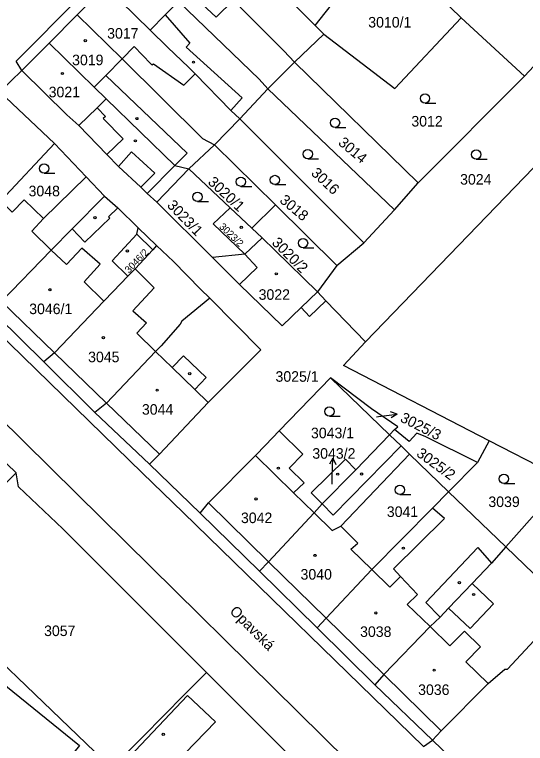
# Model space of a CAD drawing. Extents: x -527335 to -526256, y -1079142 to -1077836.
# Drawn here: x -526659.5 to -526577.1, y -1078831.7 to -1078714.2 of the extents above; entities that cross this region are included whole.
import ezdxf

# ---------------------------------------------------------------- set-up
doc = ezdxf.new("R2010")
doc.units = 0
for name, color, linetype in [('Hranice parcel', 7, 'Continuous'), ('Parcelní čísla', 7, 'Continuous'), ('Pop  PČ popisy', 7, 'Continuous'), ('Vnitřní kresba', 7, 'Continuous'), ('Značky budov', 7, 'Continuous'), ('Značky kultur', 7, 'Continuous')]:
    doc.layers.add(name, color=color, linetype=linetype)

msp = doc.modelspace()

# ---------------------------------------------------------------- linework, layer by layer
at = {"layer": 'Hranice parcel'}
for p, q in [((-526587.53, -1078714.71), (-526598.14, -1078704.26)), ((-526649.43, -1078714.21), (-526644.88, -1078709.64)), ((-526653.96, -1078718.78), (-526649.43, -1078714.21)), ((-526587.53, -1078714.71), (-526577.27, -1078724.14)), ((-526577.27, -1078724.14), (-526569.24, -1078715.32)), ((-526611.06, -1078715.96), (-526609.66, -1078717.36)), ((-526614.38, -1078721.84), (-526609.66, -1078717.36)), ((-526658.35, -1078723.2), (-526653.96, -1078718.78)), ((-526618.7, -1078726.19), (-526614.38, -1078721.84)), ((-526614.38, -1078721.84), (-526594.44, -1078741.33)), ((-526658.35, -1078723.2), (-526661.96, -1078726.67)), ((-526594.44, -1078741.33), (-526577.27, -1078724.14)), ((-526661.96, -1078726.67), (-526653.1, -1078734.98)), ((-526623.18, -1078731.02), (-526618.7, -1078726.19)), ((-526618.7, -1078726.19), (-526598.24, -1078745.67)), ((-526627.28, -1078735.22), (-526623.18, -1078731.02)), ((-526623.18, -1078731.02), (-526603.21, -1078751.02)), ((-526602.93, -1078766.96), (-526568.24, -1078730.99)), ((-526653.1, -1078734.98), (-526661.77, -1078744.22)), ((-526653.1, -1078734.98), (-526647.98, -1078740.34)), ((-526631.45, -1078739.09), (-526627.28, -1078735.22)), ((-526627.28, -1078735.22), (-526617.47, -1078744.89)), ((-526636.59, -1078744.44), (-526631.45, -1078739.09)), ((-526624.76, -1078745.36), (-526631.45, -1078739.09)), ((-526647.98, -1078740.34), (-526645, -1078743.45)), ((-526598.24, -1078745.67), (-526594.44, -1078741.33)), ((-526627.59, -1078753.38), (-526636.59, -1078744.44)), ((-526621.29, -1078748.61), (-526624.76, -1078745.36)), ((-526621.29, -1078748.61), (-526617.47, -1078744.89)), ((-526617.47, -1078744.89), (-526607.57, -1078754.64)), ((-526603.21, -1078751.02), (-526598.24, -1078745.67)), ((-526639.57, -1078748.56), (-526636.62, -1078751.43)), ((-526619.61, -1078750.18), (-526621.29, -1078748.61)), ((-526619.61, -1078750.18), (-526622.42, -1078752.83)), ((-526607.57, -1078754.64), (-526603.21, -1078751.02)), ((-526622.42, -1078752.83), (-526627.59, -1078753.38)), ((-526607.57, -1078754.64), (-526610.69, -1078758.91)), ((-526609.32, -1078760.34), (-526610.69, -1078758.91)), ((-526602.93, -1078766.96), (-526609.32, -1078760.34)), ((-526654.83, -1078770.18), (-526663.23, -1078761.88)), ((-526646.57, -1078778.36), (-526654.83, -1078770.18)), ((-526608.58, -1078772.78), (-526616.85, -1078781.33)), ((-526599.06, -1078781.96), (-526608.58, -1078772.78)), ((-526637.79, -1078786.68), (-526646.57, -1078778.36)), ((-526598.24, -1078781.1), (-526599.06, -1078781.96)), ((-526599.06, -1078781.96), (-526604.48, -1078787.61)), ((-526659.25, -1078788.06), (-526664.27, -1078783.3)), ((-526583, -1078782.94), (-526584.89, -1078786.43)), ((-526606.9, -1078796.68), (-526595.85, -1078785.05)), ((-526589.53, -1078791.15), (-526595.85, -1078785.05)), ((-526637.79, -1078786.68), (-526629.58, -1078794.56)), ((-526584.89, -1078786.43), (-526589.53, -1078791.15)), ((-526674.52, -1078803.28), (-526659.25, -1078788.06)), ((-526580.33, -1078800.02), (-526571, -1078789.45)), ((-526589.53, -1078791.15), (-526592.12, -1078793.79)), ((-526580.33, -1078800.02), (-526589.53, -1078791.15)), ((-526609.94, -1078793.08), (-526611.24, -1078794.52)), ((-526592.12, -1078793.79), (-526601.91, -1078803.67)), ((-526620.01, -1078803.95), (-526629.58, -1078794.56)), ((-526580.33, -1078800.02), (-526582.64, -1078802.63)), ((-526570.48, -1078809.52), (-526580.33, -1078800.02)), ((-526620.01, -1078803.95), (-526610.75, -1078813.07)), ((-526610.75, -1078813.07), (-526601.44, -1078822.23)), ((-526615.23, -1078833.62), (-526628.58, -1078820.26)), ((-526601.44, -1078822.23), (-526592.15, -1078831.2))]:
    msp.add_line(p, q, dxfattribs=at)
for points in [[(-526736.02, -1078622.71), (-526735.76, -1078656.09), (-526735.85, -1078660.53), (-526735.52, -1078663.69), (-526734.95, -1078666.12), (-526732.77, -1078674.37), (-526729.8, -1078686.09), (-526729.09, -1078688.53), (-526728.19, -1078690.47), (-526724.67, -1078698.8), (-526723.91, -1078700.57), (-526723.02, -1078702.2), (-526717.26, -1078711.17), (-526716.15, -1078712.7), (-526714.92, -1078714.22), (-526690.33, -1078738.18), (-526681.83, -1078746.32), (-526638.92, -1078788.12), (-526632.34, -1078794.49), (-526593.57, -1078832.2), (-526592.15, -1078831.2)], [(-526611.06, -1078715.96), (-526605, -1078708.2), (-526623.89, -1078688.51)], [(-526631.31, -1078695.96), (-526624.08, -1078702.91), (-526622.14, -1078704.85), (-526618.3, -1078708.7), (-526611.06, -1078715.96)], [(-526635.79, -1078700.47), (-526628.55, -1078707.46), (-526625.07, -1078711.01), (-526624.47, -1078711.62), (-526624.22, -1078711.87), (-526622.06, -1078714.05), (-526616.13, -1078720.06), (-526614.38, -1078721.84)], [(-526640.35, -1078705.07), (-526633.11, -1078712.1), (-526620.07, -1078724.6), (-526618.7, -1078726.19)], [(-526644.88, -1078709.64), (-526637.64, -1078716.69), (-526634.89, -1078719.43), (-526631.42, -1078722.73), (-526630.43, -1078723.74), (-526624.67, -1078729.64), (-526623.18, -1078731.02)], [(-526649.43, -1078714.21), (-526642.17, -1078721.31), (-526629.23, -1078734.17), (-526627.28, -1078735.22)], [(-526609.66, -1078717.36), (-526598.23, -1078726.12), (-526587.53, -1078714.71)], [(-526653.96, -1078718.78), (-526646.7, -1078725.9), (-526644.75, -1078727.79), (-526633.7, -1078738.55), (-526631.45, -1078739.09)], [(-526636.59, -1078744.44), (-526638.15, -1078743.02), (-526639.19, -1078742.04), (-526642.78, -1078738.7), (-526644.65, -1078736.76), (-526649.18, -1078732.07), (-526651.08, -1078730.36), (-526658.35, -1078723.2)], [(-526647.98, -1078740.34), (-526654.86, -1078747.07), (-526657.96, -1078744.05), (-526659.89, -1078746.05), (-526661.77, -1078744.22)], [(-526645, -1078743.45), (-526650.23, -1078748.74), (-526653.6, -1078752.16), (-526661.65, -1078760.47), (-526663.23, -1078761.88)], [(-526645, -1078743.45), (-526642.89, -1078745.33), (-526639.57, -1078748.56)], [(-526622.42, -1078752.83), (-526627.5, -1078747.94), (-526624.76, -1078745.36)], [(-526641.26, -1078756.38), (-526643.79, -1078753.91), (-526639.82, -1078749.58), (-526639.57, -1078748.56)], [(-526610.69, -1078758.91), (-526617.5, -1078752.24), (-526619.61, -1078750.18)], [(-526636.62, -1078751.43), (-526637.23, -1078752.14), (-526640.1, -1078755.16), (-526641.26, -1078756.38)], [(-526636.62, -1078751.43), (-526633.89, -1078754), (-526629.56, -1078758.49), (-526628.06, -1078759.94)], [(-526609.32, -1078760.34), (-526611.96, -1078762.87), (-526613.33, -1078761.44), (-526616.39, -1078764.37), (-526623.24, -1078757.7), (-526627.59, -1078753.38)], [(-526641.26, -1078756.38), (-526643.65, -1078758.85), (-526645.13, -1078760.38), (-526653.11, -1078768.71), (-526654.83, -1078770.18)], [(-526628.06, -1078759.94), (-526632.57, -1078763.6), (-526632.8, -1078764.12), (-526635.9, -1078767.6), (-526636.79, -1078768.49), (-526644.7, -1078776.83), (-526646.57, -1078778.36)], [(-526628.06, -1078759.94), (-526619.84, -1078768.26), (-526628.33, -1078776.71), (-526636.17, -1078785.07), (-526637.79, -1078786.68)], [(-526583, -1078782.94), (-526606.49, -1078770.77), (-526602.93, -1078766.96)], [(-526598.24, -1078781.1), (-526597.7, -1078780.64), (-526601.99, -1078777.75), (-526608.58, -1078772.78)], [(-526584.89, -1078786.43), (-526593.2, -1078782.26), (-526594.65, -1078781.7), (-526595.87, -1078783.03), (-526598.24, -1078781.1)], [(-526629.58, -1078794.56), (-526628.25, -1078792.92), (-526620.7, -1078785.28), (-526619.04, -1078783.6), (-526616.85, -1078781.33)], [(-526616.85, -1078781.33), (-526613.02, -1078785.09), (-526615.22, -1078787.34), (-526612.82, -1078789.68), (-526614.53, -1078791.3), (-526611.24, -1078794.52)], [(-526595.85, -1078785.05), (-526597.21, -1078783.74), (-526599.06, -1078781.96)], [(-526568.95, -1078787.13), (-526573.17, -1078787.97), (-526583, -1078782.94)], [(-526609.94, -1078793.08), (-526611.7, -1078791.28), (-526606.18, -1078785.87), (-526604.48, -1078787.61)], [(-526628.58, -1078820.26), (-526651.76, -1078797.09), (-526658.89, -1078790.32), (-526659.25, -1078788.06)], [(-526604.48, -1078787.61), (-526604.69, -1078787.82), (-526609.94, -1078793.08)], [(-526659.11, -1078844.46), (-526705.02, -1078807.32), (-526694.99, -1078794.92), (-526649.08, -1078832.06), (-526659.11, -1078844.46)], [(-526611.24, -1078794.52), (-526618.56, -1078802.42), (-526620.01, -1078803.95)], [(-526601.91, -1078803.67), (-526605.28, -1078800.36), (-526604.15, -1078799.44), (-526606.9, -1078796.68)], [(-526674.52, -1078803.28), (-526675.67, -1078805.16), (-526643.83, -1078835.71)], [(-526582.64, -1078802.63), (-526585.74, -1078805.91), (-526589.53, -1078809.92), (-526590.9, -1078811.36), (-526592.53, -1078812.87), (-526600, -1078820.6), (-526601.44, -1078822.23)], [(-526601.91, -1078803.67), (-526609.3, -1078811.48), (-526610.75, -1078813.07)], [(-526592.15, -1078831.2), (-526590.73, -1078829.68), (-526583.18, -1078822.03), (-526580.48, -1078819.73), (-526580.05, -1078819.71), (-526573.56, -1078812.8)], [(-526643.83, -1078835.71), (-526634.9, -1078826.67), (-526632.69, -1078824.43), (-526628.58, -1078820.26)], [(-526631.64, -1078823.97), (-526642.87, -1078835.86), (-526638.55, -1078840.04), (-526627.14, -1078828.22), (-526631.64, -1078823.97)], [(-526592.15, -1078831.2), (-526581.94, -1078841.02), (-526570.51, -1078852.02), (-526552.02, -1078869.8)]]:
    msp.add_lwpolyline(points, dxfattribs=at)
at = {"layer": 'Pop  PČ popisy'}
for p, q in [((-526600.83, -1078778.98), (-526597.85, -1078778.61)), ((-526597.85, -1078778.61), (-526598.91, -1078778.24)), ((-526597.85, -1078778.61), (-526598.78, -1078779.23)), ((-526601.17, -1078779.02), (-526600.83, -1078778.98)), ((-526608.2, -1078785.7), (-526608.73, -1078786.68)), ((-526608.3, -1078788.7), (-526608.2, -1078785.7)), ((-526608.2, -1078785.7), (-526607.73, -1078786.72)), ((-526608.33, -1078789.89), (-526608.3, -1078788.7))]:
    msp.add_line(p, q, dxfattribs=at)
at = {"layer": 'Vnitřní kresba'}
for p, q in [((-526659.29, -1078721.72), (-526631.42, -1078693.62)), ((-526635.23, -1078714.25), (-526633.11, -1078712.1)), ((-526637.64, -1078716.69), (-526635.23, -1078714.25)), ((-526635.23, -1078714.25), (-526631.26, -1078718.78)), ((-526631.26, -1078718.78), (-526631.87, -1078719.46)), ((-526642.17, -1078721.31), (-526640.24, -1078719.35)), ((-526640.24, -1078719.35), (-526637.56, -1078722.13)), ((-526631.87, -1078719.46), (-526622.85, -1078727.63)), ((-526658.35, -1078723.2), (-526659.29, -1078721.72)), ((-526644.82, -1078723.99), (-526642.17, -1078721.31)), ((-526637.56, -1078722.13), (-526637.37, -1078722.32)), ((-526637.37, -1078722.32), (-526637.13, -1078722.15)), ((-526637.13, -1078722.15), (-526632.25, -1078725.57)), ((-526644.82, -1078723.99), (-526646.7, -1078725.9)), ((-526631.7, -1078736.54), (-526644.82, -1078723.99)), ((-526632.25, -1078725.57), (-526630.43, -1078723.74)), ((-526646.23, -1078729.22), (-526644.75, -1078727.79)), ((-526622.85, -1078727.63), (-526624.67, -1078729.64)), ((-526649.18, -1078732.07), (-526646.23, -1078729.22)), ((-526646.23, -1078729.22), (-526644.87, -1078730.62)), ((-526644.87, -1078730.62), (-526645.23, -1078730.97)), ((-526645.23, -1078730.97), (-526642, -1078734.21)), ((-526642, -1078734.21), (-526644.65, -1078736.76)), ((-526642.78, -1078738.7), (-526640.69, -1078736.32)), ((-526640.69, -1078736.32), (-526636.89, -1078739.74)), ((-526631.7, -1078736.54), (-526633.7, -1078738.55)), ((-526633.7, -1078738.55), (-526638.15, -1078743.02)), ((-526636.89, -1078739.74), (-526639.19, -1078742.04)), ((-526644.39, -1078746.78), (-526642.89, -1078745.33)), ((-526654.86, -1078747.07), (-526656.74, -1078749.11)), ((-526648.19, -1078750.86), (-526644.19, -1078747)), ((-526644.19, -1078747), (-526644.39, -1078746.78)), ((-526649.54, -1078791.39), (-526693.26, -1078748.65)), ((-526656.74, -1078749.11), (-526653.6, -1078752.16)), ((-526650.23, -1078748.74), (-526648.19, -1078750.86)), ((-526637.23, -1078752.14), (-526639.82, -1078749.58)), ((-526651.18, -1078754.51), (-526653.6, -1078752.16)), ((-526648.69, -1078751.88), (-526651.18, -1078754.51)), ((-526645.72, -1078754.44), (-526648.69, -1078751.88)), ((-526622.42, -1078752.83), (-526620.38, -1078754.98)), ((-526648.33, -1078757.27), (-526645.72, -1078754.44)), ((-526640.1, -1078755.16), (-526637.03, -1078758.23)), ((-526620.38, -1078754.98), (-526623.24, -1078757.7)), ((-526645.13, -1078760.38), (-526648.33, -1078757.27)), ((-526637.03, -1078758.23), (-526640.44, -1078761.95)), ((-526613.33, -1078761.44), (-526610.69, -1078758.91)), ((-526661.65, -1078760.47), (-526653.11, -1078768.71)), ((-526640.44, -1078761.95), (-526638.27, -1078763.9)), ((-526639.8, -1078765.56), (-526638.27, -1078763.9)), ((-526636.79, -1078768.49), (-526639.8, -1078765.56)), ((-526644.7, -1078776.83), (-526653.11, -1078768.71)), ((-526634.12, -1078771.08), (-526636.79, -1078768.49)), ((-526632.31, -1078769.22), (-526634.12, -1078771.08)), ((-526628.61, -1078772.7), (-526632.31, -1078769.22)), ((-526630.48, -1078774.62), (-526634.12, -1078771.08)), ((-526630.48, -1078774.62), (-526628.61, -1078772.7)), ((-526628.33, -1078776.71), (-526630.48, -1078774.62)), ((-526636.17, -1078785.07), (-526644.7, -1078776.83)), ((-526608.16, -1078794.9), (-526597.21, -1078783.74)), ((-526614.53, -1078791.3), (-526620.7, -1078785.28)), ((-526598.1, -1078842.1), (-526649.54, -1078791.39)), ((-526618.56, -1078802.42), (-526628.25, -1078792.92)), ((-526609.94, -1078793.08), (-526608.16, -1078794.9)), ((-526590.17, -1078795.43), (-526592.12, -1078793.79)), ((-526608.31, -1078797.39), (-526611.24, -1078794.52)), ((-526598.44, -1078803.57), (-526590.17, -1078795.43)), ((-526608.31, -1078797.39), (-526606.9, -1078796.68)), ((-526584.83, -1078800.13), (-526593.19, -1078808.99)), ((-526584.83, -1078800.13), (-526582.64, -1078802.63)), ((-526609.3, -1078811.48), (-526618.56, -1078802.42)), ((-526599.02, -1078806.5), (-526601.91, -1078803.67)), ((-526597.31, -1078804.77), (-526598.44, -1078803.57)), ((-526597.31, -1078804.77), (-526599.02, -1078806.5)), ((-526594.57, -1078807.69), (-526597.31, -1078804.77)), ((-526596.19, -1078809.28), (-526594.57, -1078807.69)), ((-526592.53, -1078812.87), (-526596.19, -1078809.28)), ((-526593.19, -1078808.99), (-526590.9, -1078811.36)), ((-526609.3, -1078811.48), (-526600, -1078820.6)), ((-526589.35, -1078815.98), (-526592.53, -1078812.87)), ((-526586.99, -1078813.58), (-526589.35, -1078815.98)), ((-526584.39, -1078816.14), (-526586.99, -1078813.58)), ((-526586.74, -1078818.54), (-526584.39, -1078816.14)), ((-526583.18, -1078822.03), (-526586.74, -1078818.54)), ((-526600, -1078820.6), (-526590.73, -1078829.68))]:
    msp.add_line(p, q, dxfattribs=at)
for points in [[(-526624.22, -1078711.87), (-526627.03, -1078714.61), (-526631.46, -1078710.42)], [(-526585.74, -1078805.91), (-526582.32, -1078809.2), (-526586.08, -1078813.19), (-526589.53, -1078809.92)]]:
    msp.add_lwpolyline(points, dxfattribs=at)
at = {"layer": 'Značky budov'}
for centre in [(-526648.12, -1078718.41), (-526630.67, -1078721.86), (-526651.81, -1078723.7), (-526639.8, -1078730.96), (-526640.05, -1078734.55), (-526646.56, -1078746.95), (-526622.97, -1078748.5), (-526641.34, -1078752.31), (-526617.32, -1078756), (-526653.83, -1078758.56), (-526645.21, -1078766.29), (-526631.29, -1078772.1), (-526636.53, -1078774.74), (-526616.98, -1078787.32), (-526607.42, -1078788.29), (-526603.57, -1078788.27), (-526620.59, -1078792.28), (-526596.83, -1078800.23), (-526611.08, -1078801.39), (-526587.8, -1078805.79), (-526585.5, -1078807.7), (-526601.27, -1078810.66), (-526591.87, -1078819.88), (-526635.54, -1078830.23)]:
    msp.add_circle(centre, 0.175, dxfattribs=at)
at = {"layer": 'Značky kultur'}
for p, q in [((-526593.34, -1078728.46), (-526591.59, -1078728.46)), ((-526607.85, -1078732.39), (-526606.1, -1078732.39)), ((-526612.25, -1078737.44), (-526610.5, -1078737.44)), ((-526585.07, -1078737.5), (-526583.32, -1078737.5)), ((-526654.76, -1078739.76), (-526653.01, -1078739.76)), ((-526623.04, -1078741.89), (-526621.29, -1078741.89)), ((-526617.54, -1078741.61), (-526615.79, -1078741.61)), ((-526630.03, -1078744.34), (-526628.28, -1078744.34)), ((-526613.01, -1078751.78), (-526611.26, -1078751.78)), ((-526608.76, -1078778.94), (-526607.01, -1078778.94)), ((-526580.62, -1078789.79), (-526578.87, -1078789.79)), ((-526597.38, -1078791.57), (-526595.63, -1078791.57))]:
    msp.add_line(p, q, dxfattribs=at)
for centre in [(-526593.34, -1078727.71), (-526607.85, -1078731.64), (-526612.25, -1078736.69), (-526585.07, -1078736.75), (-526654.76, -1078739.01), (-526623.04, -1078741.14), (-526617.54, -1078740.86), (-526630.03, -1078743.59), (-526613.01, -1078751.03), (-526608.76, -1078778.19), (-526580.62, -1078789.04), (-526597.38, -1078790.82)]:
    msp.add_circle(centre, 0.75, dxfattribs=at)

# ---------------------------------------------------------------- texts
at = {"layer": 'Parcelní čísla'}
for s, p in [('3010/1', (-526602.49, -1078716.28)), ('3017', (-526644.6, -1078718.07)), ('3019', (-526650.25, -1078722.36)), ('3021', (-526654.03, -1078727.53)), ('3012', (-526595.54, -1078732.24)), ('3024', (-526587.68, -1078741.61)), ('3048', (-526657.27, -1078743.49)), ('3022', (-526620.17, -1078760.18)), ('3046/1', (-526657.17, -1078762.49)), ('3045', (-526647.67, -1078770.24)), ('3025/1', (-526617.45, -1078773.39)), ('3044', (-526638.99, -1078778.7)), ('3043/1', (-526611.73, -1078782.5)), ('3043/2', (-526611.51, -1078785.8)), ('3039', (-526583.12, -1078793.59)), ('3041', (-526599.5, -1078795.19)), ('3042', (-526623.02, -1078796.18)), ('3040', (-526613.41, -1078805.29)), ('3057', (-526654.77, -1078814.39)), ('3038', (-526603.81, -1078814.53)), ('3036', (-526594.45, -1078823.89))]:
    msp.add_text(s, height=1.7, dxfattribs=at).set_placement(p)
for s, height, rotation, p in [('3014', 1.7, 320, (-526607.46, -1078735.06)), ('3016', 1.7, 317, (-526611.83, -1078739.91)), ('3020/1', 1.7, 317, (-526628.48, -1078741.36)), ('3018', 1.7, 320, (-526616.91, -1078744.34)), ('3023/1', 1.7, 314, (-526635.05, -1078745.05)), ('3023/2', 1.14, 316, (-526626.62, -1078748.5)), ('3020/2', 1.7, 315, (-526618.16, -1078751.1)), ('3046/2', 1.14, 46, (-526641.07, -1078755.98)), ('3025/3', 1.7, 333, (-526597.48, -1078779.73)), ('3025/2', 1.7, 324, (-526594.86, -1078785.26))]:
    msp.add_text(s, height=height, rotation=rotation, dxfattribs=at).set_placement(p)
at = {"layer": 'Pop  PČ popisy'}
msp.add_text('Opavská', height=1.7, rotation=315, dxfattribs=at).set_placement((-526624.95, -1078810.53))

doc.saveas('drawing.dxf')
